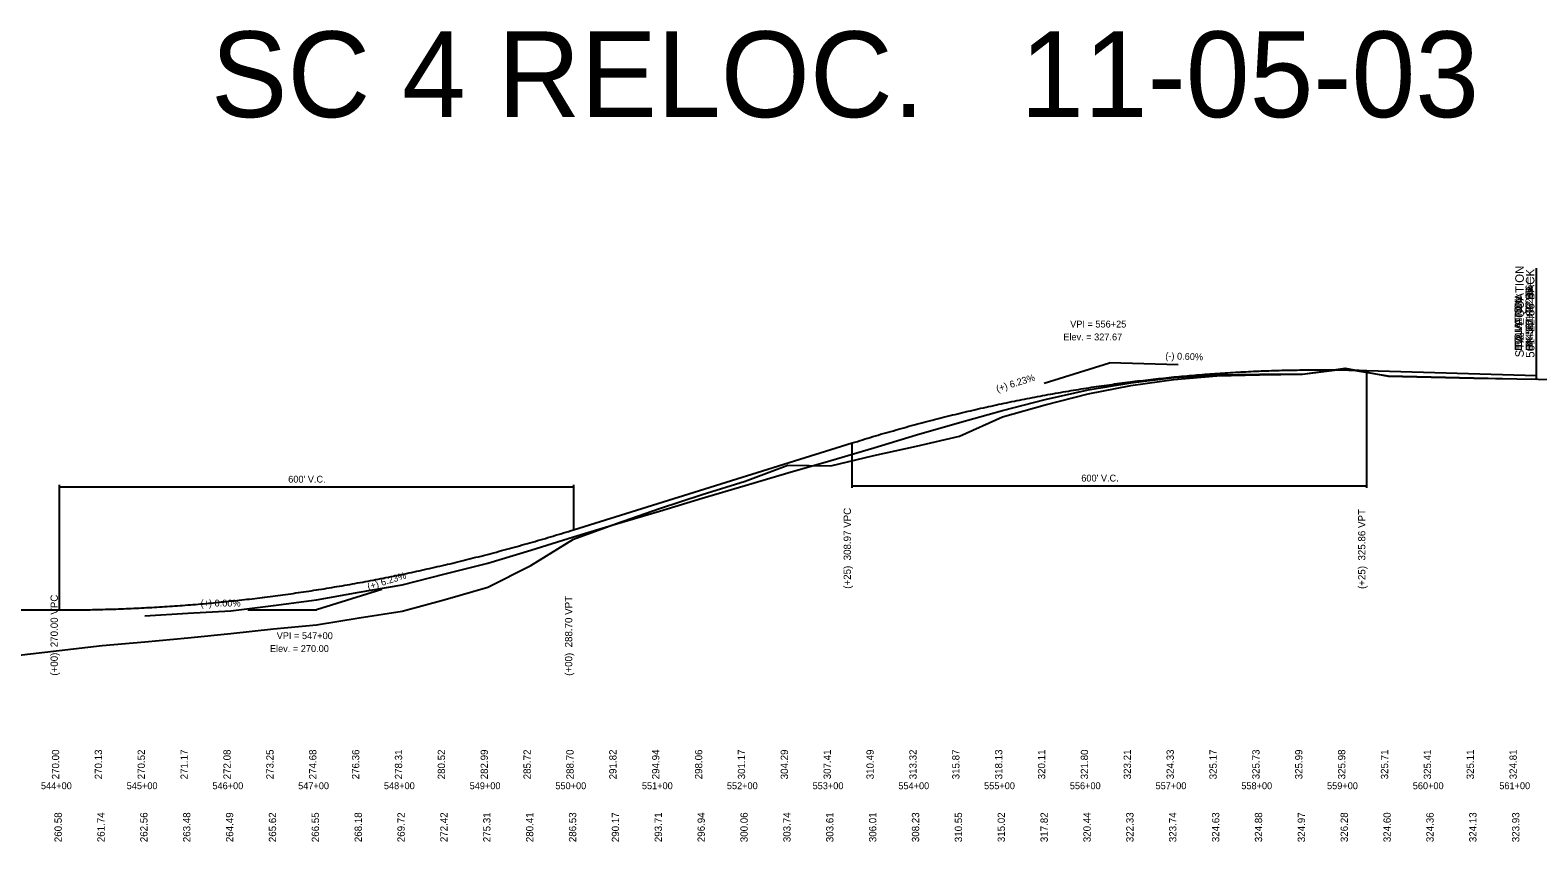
# Model space of a CAD drawing. Extents: x 1354 to 11940, y 17935 to 18885.
# Drawn here: x 8306 to 10064, y 17938 to 18885 of the extents above; entities that cross this region are included whole.
import ezdxf

# ---------------------------------------------------------------- set-up
doc = ezdxf.new("R2010")
doc.units = 0
for name, color, linetype in [('Level 1', 7, 'Continuous'), ('Level 40', 7, 'Continuous'), ('Level 41', 7, 'Continuous'), ('Level 42', 7, 'Continuous'), ('Level 43', 7, 'Continuous'), ('Level 45', 7, 'Continuous')]:
    doc.layers.add(name, color=color, linetype=linetype)

msp = doc.modelspace()

# ---------------------------------------------------------------- linework, layer by layer
at = {"layer": 'Level 1'}
msp.add_line((10062.6, 18477.7), (10062.6, 18577.7), dxfattribs=at)
at = {"layer": 'Level 40'}
for points in [[(8289.7, 18155.6), (8339.7, 18161.4), (8389.7, 18167.2), (8439.7, 18171.3), (8489.7, 18175.9), (8539.7, 18181), (8589.7, 18186.6), (8639.7, 18191.3), (8689.7, 18199.4), (8739.7, 18207.1), (8789.7, 18220.6), (8839.7, 18235), (8889.7, 18260.5), (8939.7, 18291.1), (8989.7, 18309.4), (9039.7, 18327), (9089.7, 18343.2), (9139.7, 18358.8), (9189.7, 18377.2), (9239.7, 18376.6), (9289.7, 18388.5), (9339.7, 18399.7), (9389.7, 18411.2), (9439.7, 18433.6), (9489.7, 18447.6), (9539.7, 18460.7), (9589.7, 18470.1), (9639.7, 18477.2), (9689.7, 18481.7), (9739.7, 18482.9), (9789.7, 18483.4), (9839.7, 18489.9), (9889.7, 18481.5), (9939.7, 18480.3), (9989.7, 18479.2), (10039.7, 18478.1), (10062.6, 18477.7)], [(8439.7, 18201.8), (8489.7, 18204.7), (8539.7, 18207.5), (8589.7, 18213.9), (8639.7, 18220.2), (8689.7, 18229.1), (8739.7, 18238), (8789.7, 18250.5), (8839.7, 18263.1), (8889.7, 18278.4), (8939.7, 18293.8), (8989.7, 18308.8), (9039.7, 18323.8), (9089.7, 18338.8), (9139.7, 18353.6), (9189.7, 18368.6), (9239.7, 18382.9), (9289.7, 18397.7), (9339.7, 18412.6), (9389.7, 18427.2), (9439.7, 18441.1), (9489.7, 18454.1), (9539.7, 18465.2), (9589.7, 18473.5), (9639.7, 18479.5), (9689.7, 18482.9), (9739.7, 18483.6), (9789.7, 18483.4), (9839.7, 18490.4), (9889.7, 18481.3), (9939.7, 18480), (9989.7, 18478.9), (10039.7, 18478.1), (10089.7, 18477.2)]]:
    msp.add_lwpolyline(points, dxfattribs=at)
at = {"layer": 'Level 41'}
for p, q in [((10062.6, 18484.8), (10062.6, 18607.2)), ((10062.6, 18481.9), (10062.6, 18604.3)), ((10062.6, 18480.3), (10062.6, 18602.7)), ((9488.4, 18473), (9564.7, 18496.9)), ((9644.7, 18494.4), (9564.7, 18496.9)), ((9864.7, 18350.8), (9864.7, 18487.8)), ((9264.7, 18350.8), (9264.7, 18403.3)), ((8339.7, 18354.5), (8339.7, 18208.5)), ((8339.7, 18352), (8939.7, 18352)), ((8939.7, 18354.5), (8939.7, 18302)), ((9264.7, 18353.3), (9864.7, 18353.3)), ((8716.1, 18232.3), (8639.7, 18208.5)), ((8559.7, 18208.5), (8639.7, 18208.5))]:
    msp.add_line(p, q, dxfattribs=at)
at = {"layer": 'Level 45'}
for p, q in [((9864.7, 18487.8), (10062.6, 18481.9)), ((8939.7, 18302), (9264.7, 18403.3)), ((4474.7, 18208.5), (8339.7, 18208.5))]:
    msp.add_line(p, q, dxfattribs=at)
for points in [[(9264.7, 18403.3), (9276.7, 18407), (9288.7, 18410.7), (9300.7, 18414.2), (9312.7, 18417.6), (9324.7, 18421), (9336.7, 18424.3), (9348.7, 18427.5), (9360.7, 18430.6), (9372.7, 18433.7), (9384.7, 18436.6), (9396.7, 18439.5), (9408.7, 18442.3), (9420.7, 18445), (9432.7, 18447.7), (9444.7, 18450.2), (9456.7, 18452.7), (9468.7, 18455.1), (9480.7, 18457.4), (9492.7, 18459.6), (9504.7, 18461.7), (9516.7, 18463.8), (9528.7, 18465.8), (9540.7, 18467.7), (9552.7, 18469.5), (9564.7, 18471.2), (9576.7, 18472.9), (9588.7, 18474.4), (9600.7, 18475.9), (9612.7, 18477.3), (9624.7, 18478.6), (9636.7, 18479.9), (9648.7, 18481), (9660.7, 18482.1), (9672.7, 18483.1), (9684.7, 18484), (9696.7, 18484.8), (9708.7, 18485.6), (9720.7, 18486.2), (9732.7, 18486.8), (9744.7, 18487.3), (9756.7, 18487.7), (9768.7, 18488.1), (9780.7, 18488.3), (9792.7, 18488.5), (9804.7, 18488.6), (9816.7, 18488.6), (9828.7, 18488.5), (9840.7, 18488.4), (9852.7, 18488.1), (9864.7, 18487.8)], [(8339.7, 18208.5), (8351.7, 18208.5), (8363.7, 18208.7), (8375.7, 18208.8), (8387.7, 18209.1), (8399.7, 18209.4), (8411.7, 18209.8), (8423.7, 18210.3), (8435.7, 18210.9), (8447.7, 18211.5), (8459.7, 18212.2), (8471.7, 18213), (8483.7, 18213.9), (8495.7, 18214.8), (8507.7, 18215.8), (8519.7, 18216.9), (8531.7, 18218.1), (8543.7, 18219.3), (8555.7, 18220.6), (8567.7, 18222), (8579.7, 18223.5), (8591.7, 18225), (8603.7, 18226.6), (8615.7, 18228.3), (8627.7, 18230), (8639.7, 18231.9), (8651.7, 18233.8), (8663.7, 18235.8), (8675.7, 18237.8), (8687.7, 18240), (8699.7, 18242.2), (8711.7, 18244.5), (8723.7, 18246.8), (8735.7, 18249.2), (8747.7, 18251.7), (8759.7, 18254.3), (8771.7, 18257), (8783.7, 18259.7), (8795.7, 18262.5), (8807.7, 18265.4), (8819.7, 18268.4), (8831.7, 18271.4), (8843.7, 18274.5), (8855.7, 18277.7), (8867.7, 18280.9), (8879.7, 18284.3), (8891.7, 18287.7), (8903.7, 18291.1), (8915.7, 18294.7), (8927.7, 18298.3), (8939.7, 18302)]]:
    msp.add_spline(points, degree=3, dxfattribs=at)

# ---------------------------------------------------------------- texts
at = {"layer": 'Level 1'}
msp.add_text('SC 4 RELOC.   11-05-03', height=100, dxfattribs=at).set_placement((8516.7, 18783.2))
for s, p in [('STA.  EQUATION', (10047.9, 18503.1)), ('561+22.86 BACK', (10060.3, 18502.6))]:
    msp.add_text(s, height=10, rotation=90, dxfattribs=at).set_placement(p)
at = {"layer": 'Level 41'}
for s, height, rotation, p in [('BK 561+22.86 =', 8.5, 90, (10058.4, 18515.4)), ('BK 561+22.86 =', 8.5, 90, (10058.4, 18512.5)), ('BK 561+22.86 =', 8.5, 90, (10058.4, 18510.9)), ('EQUATION:', 8.5, 90, (10045.6, 18515.4)), ('EQUATION:', 8.5, 90, (10045.6, 18512.5)), ('EQUATION:', 8.5, 90, (10045.6, 18510.9)), ('(-) 0.60%', 8, 358.2747, (9629.7, 18500.9)), ('(+) 6.23%', 8, 17.3138, (9433.9, 18462.4)), ('(+25)  308.97 VPC', 8.5, 90, (9263.1, 18233.2)), ('(+25)  325.86 VPT', 8.5, 90, (9863.1, 18233)), ('(+) 6.23%', 8, 17.3138, (8700.5, 18231.6)), ('(+00)  270.00 VPC', 8.5, 90, (8338.1, 18131.9)), ('(+00)  288.70 VPT', 8.5, 90, (8938.1, 18131.7))]:
    msp.add_text(s, height=height, rotation=rotation, dxfattribs=at).set_placement(p)
for s, p in [('VPI = 556+25', (9518.8, 18537.9)), ('Elev. = 327.67', (9510.8, 18522.9)), ("600' V.C.", (8606.8, 18357)), ("600' V.C.", (9531.8, 18358.3)), ('(+) 0.00%', (8504.6, 18212.5)), ('VPI = 547+00', (8593.4, 18174.5)), ('Elev. = 270.00', (8585.5, 18159.5))]:
    msp.add_text(s, height=8, dxfattribs=at).set_placement(p)
at = {"layer": 'Level 42'}
for s, p in [('544+00', (8318.4, 17999.5)), ('545+00', (8418.4, 17999.5)), ('545+00', (8418.4, 17999.5)), ('546+00', (8518.4, 17999.5)), ('546+00', (8518.4, 17999.5)), ('547+00', (8618.4, 17999.5)), ('547+00', (8618.4, 17999.5)), ('548+00', (8718.4, 17999.5)), ('548+00', (8718.4, 17999.5)), ('549+00', (8818.4, 17999.5)), ('549+00', (8818.4, 17999.5)), ('550+00', (8918.4, 17999.5)), ('550+00', (8918.4, 17999.5)), ('551+00', (9019.3, 17999.5)), ('551+00', (9019.3, 17999.5)), ('552+00', (9118.4, 17999.5)), ('552+00', (9118.4, 17999.5)), ('553+00', (9218.4, 17999.5)), ('553+00', (9218.4, 17999.5)), ('554+00', (9318.4, 17999.5)), ('554+00', (9318.4, 17999.5)), ('555+00', (9418.4, 17999.5)), ('555+00', (9418.4, 17999.5)), ('556+00', (9518.4, 17999.5)), ('556+00', (9518.4, 17999.5)), ('557+00', (9618.4, 17999.5)), ('557+00', (9618.4, 17999.5)), ('558+00', (9718.4, 17999.5)), ('558+00', (9718.4, 17999.5)), ('559+00', (9818.4, 17999.5)), ('559+00', (9818.4, 17999.5)), ('560+00', (9918.4, 17999.5)), ('560+00', (9918.4, 17999.5)), ('561+00', (10019.3, 17999.5)), ('561+00', (10019.3, 17999.5))]:
    msp.add_text(s, height=8, dxfattribs=at).set_placement(p)
at = {"layer": 'Level 43'}
for s, p in [('270.00', (8339.7, 18011)), ('270.13', (8389.7, 18011)), ('270.52', (8439.7, 18011)), ('271.17', (8489.7, 18011)), ('272.08', (8539.7, 18011)), ('273.25', (8589.7, 18011)), ('274.68', (8639.7, 18011)), ('276.36', (8689.7, 18011)), ('278.31', (8739.7, 18011)), ('280.52', (8789.7, 18011)), ('282.99', (8839.7, 18011)), ('285.72', (8889.7, 18011)), ('288.70', (8939.7, 18011)), ('291.82', (8989.7, 18011)), ('294.94', (9039.7, 18011)), ('298.06', (9089.7, 18011)), ('301.17', (9139.7, 18011)), ('304.29', (9189.7, 18011)), ('307.41', (9239.7, 18011)), ('310.49', (9289.7, 18011)), ('313.32', (9339.7, 18011)), ('315.87', (9389.7, 18011)), ('318.13', (9439.7, 18011)), ('320.11', (9489.7, 18011)), ('321.80', (9539.7, 18011)), ('323.21', (9589.7, 18011)), ('324.33', (9639.7, 18011)), ('325.17', (9689.7, 18011)), ('325.73', (9739.7, 18011)), ('325.99', (9789.7, 18011)), ('325.98', (9839.7, 18011)), ('325.71', (9889.7, 18011)), ('325.41', (9939.7, 18011)), ('325.11', (9989.7, 18011)), ('324.81', (10039.7, 18011)), ('260.58', (8342.7, 17937.7)), ('261.74', (8392.7, 17937.7)), ('262.56', (8442.7, 17937.7)), ('263.48', (8492.7, 17937.7)), ('264.49', (8542.7, 17937.7)), ('265.62', (8592.7, 17937.7)), ('266.55', (8642.7, 17937.7)), ('268.18', (8692.7, 17937.7)), ('269.72', (8742.7, 17937.7)), ('272.42', (8792.7, 17937.7)), ('275.31', (8842.7, 17937.7)), ('280.41', (8892.7, 17937.7)), ('286.53', (8942.7, 17937.7)), ('290.17', (8992.7, 17937.7)), ('293.71', (9042.7, 17937.7)), ('296.94', (9092.7, 17937.7)), ('300.06', (9142.7, 17937.7)), ('303.74', (9192.7, 17937.7)), ('303.61', (9242.7, 17937.7)), ('306.01', (9292.7, 17937.7)), ('308.23', (9342.7, 17937.7)), ('310.55', (9392.7, 17937.7)), ('315.02', (9442.7, 17937.7)), ('317.82', (9492.7, 17937.7)), ('320.44', (9542.7, 17937.7)), ('322.33', (9592.7, 17937.7)), ('323.74', (9642.7, 17937.7)), ('324.63', (9692.7, 17937.7)), ('324.88', (9742.7, 17937.7)), ('324.97', (9792.7, 17937.7)), ('326.28', (9842.7, 17937.7)), ('324.60', (9892.7, 17937.7)), ('324.36', (9942.7, 17937.7)), ('324.13', (9992.7, 17937.7)), ('323.93', (10042.7, 17937.7))]:
    msp.add_text(s, height=8.5, rotation=90, dxfattribs=at).set_placement(p)

doc.saveas('drawing.dxf')
